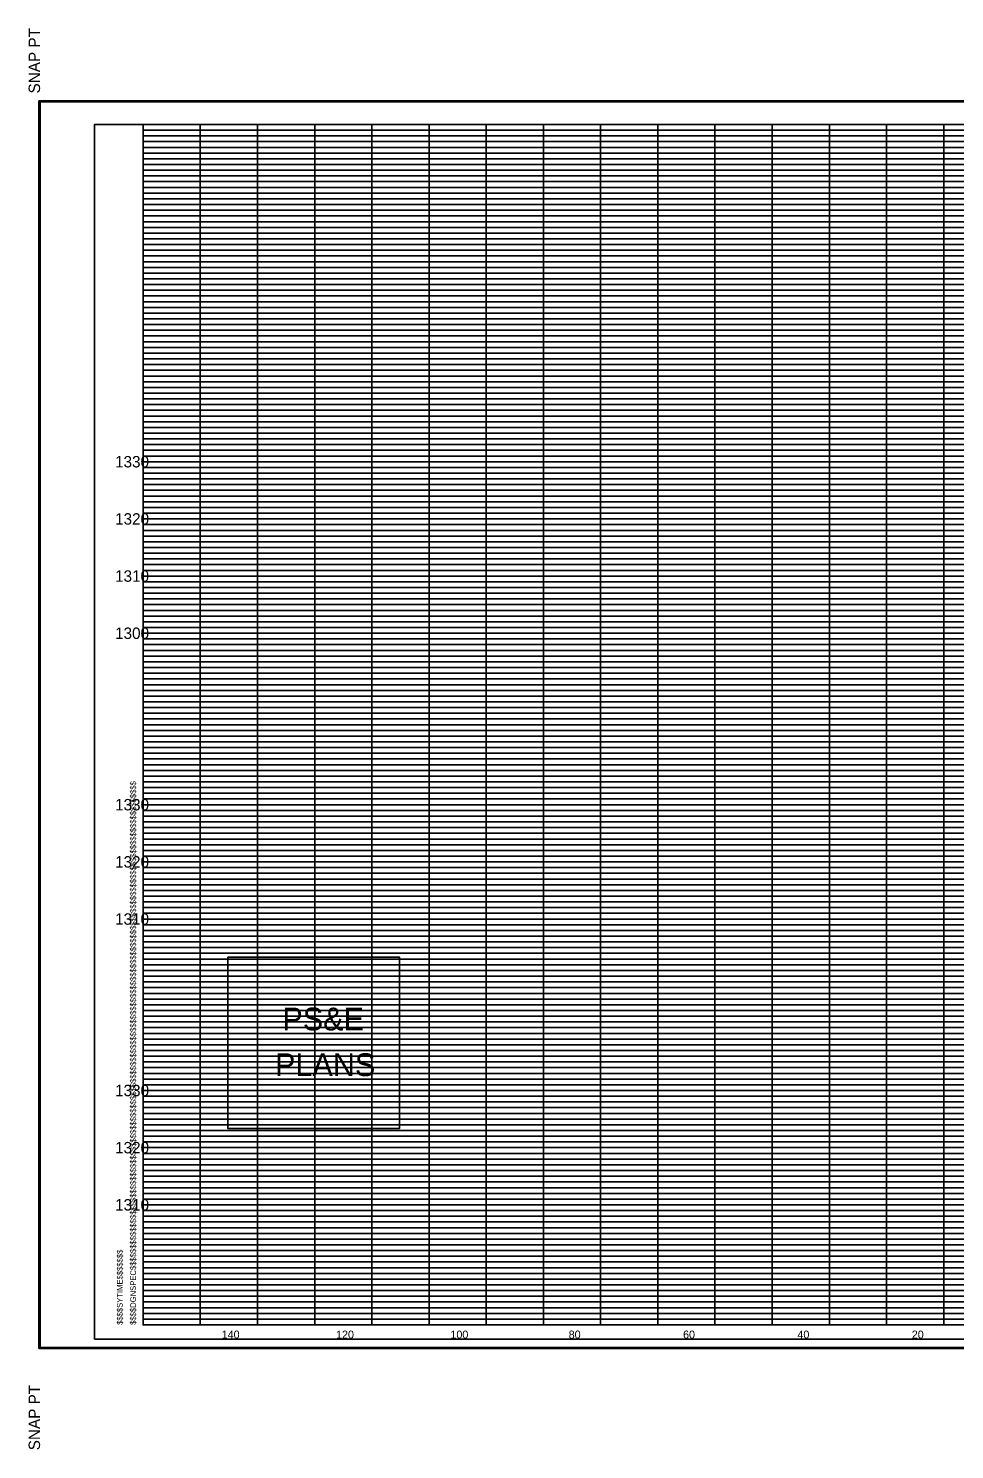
# Model space of a CAD drawing. Extents: x 980 to 1324, y 978 to 1227.
# Drawn here: x 979.7 to 1141.7, y 978 to 1226.6 of the extents above; entities that cross this region are included whole.
import ezdxf

# ---------------------------------------------------------------- set-up
doc = ezdxf.new("R2010")
doc.units = 0
for name, color, linetype in [('Default', 7, 'Continuous'), ('DESIGN - SHEET - Corner Text', 7, 'Continuous'), ('DESIGN - SHEET - Light Grid', 7, 'Continuous'), ('DESIGN - SHEET - Linework', 7, 'Continuous'), ('DESIGN - SHEET - Plot Shape', 7, 'Continuous'), ('DESIGN - TYPICAL - Text', 7, 'Continuous')]:
    doc.layers.add(name, color=color, linetype=linetype)

# ---------------------------------------------------------------- blocks, each defined once
blk = doc.blocks.new('XSTSHT')
at = {"layer": 'DESIGN - SHEET - Light Grid'}
for p, q in [((0, 20.9), (8, 20.9)), ((8, 20.9), (16, 20.9)), ((0, 20.8), (8, 20.8)), ((0, 20.7), (8, 20.7)), ((8, 20.8), (16, 20.8)), ((8, 20.7), (16, 20.7)), ((0, 20.6), (8, 20.6)), ((0, 20.5), (8, 20.5)), ((0, 20.4), (8, 20.4)), ((8, 20.6), (16, 20.6)), ((8, 20.5), (16, 20.5)), ((8, 20.4), (16, 20.4)), ((0, 20.3), (8, 20.3)), ((0, 20.2), (8, 20.2)), ((8, 20.3), (16, 20.3)), ((8, 20.2), (16, 20.2)), ((0, 20.1), (8, 20.1)), ((0, 19.9), (8, 19.9)), ((8, 20.1), (16, 20.1)), ((8, 19.9), (16, 19.9)), ((0, 19.8), (8, 19.8)), ((0, 19.7), (8, 19.7)), ((8, 19.8), (16, 19.8)), ((8, 19.7), (16, 19.7)), ((0, 19.6), (8, 19.6)), ((0, 19.5), (8, 19.5)), ((0, 19.4), (8, 19.4)), ((8, 19.6), (16, 19.6)), ((8, 19.5), (16, 19.5)), ((8, 19.4), (16, 19.4)), ((0, 19.3), (8, 19.3)), ((0, 19.2), (8, 19.2)), ((8, 19.3), (16, 19.3)), ((8, 19.2), (16, 19.2)), ((0, 19.1), (8, 19.1)), ((0, 18.9), (8, 18.9)), ((8, 19.1), (16, 19.1)), ((8, 18.9), (16, 18.9)), ((0, 18.8), (8, 18.8)), ((0, 18.7), (8, 18.7)), ((8, 18.8), (16, 18.8)), ((8, 18.7), (16, 18.7)), ((0, 18.6), (8, 18.6)), ((0, 18.5), (8, 18.5)), ((0, 18.4), (8, 18.4)), ((8, 18.6), (16, 18.6)), ((8, 18.5), (16, 18.5)), ((8, 18.4), (16, 18.4)), ((0, 18.3), (8, 18.3)), ((0, 18.2), (8, 18.2)), ((8, 18.3), (16, 18.3)), ((8, 18.2), (16, 18.2)), ((0, 18.1), (8, 18.1)), ((8, 18.1), (16, 18.1)), ((0, 17.9), (8, 17.9)), ((0, 17.8), (8, 17.8)), ((0, 17.7), (8, 17.7)), ((8, 17.9), (16, 17.9)), ((8, 17.8), (16, 17.8)), ((8, 17.7), (16, 17.7)), ((0, 17.6), (8, 17.6)), ((0, 17.5), (8, 17.5)), ((8, 17.6), (16, 17.6)), ((8, 17.5), (16, 17.5)), ((0, 17.4), (8, 17.4)), ((0, 17.3), (8, 17.3)), ((0, 17.2), (8, 17.2)), ((8, 17.4), (16, 17.4)), ((8, 17.3), (16, 17.3)), ((8, 17.2), (16, 17.2)), ((0, 17.1), (8, 17.1)), ((8, 17.1), (16, 17.1)), ((0, 16.9), (8, 16.9)), ((0, 16.8), (8, 16.8)), ((0, 16.7), (8, 16.7)), ((8, 16.9), (16, 16.9)), ((8, 16.8), (16, 16.8)), ((8, 16.7), (16, 16.7)), ((0, 16.6), (8, 16.6)), ((0, 16.5), (8, 16.5)), ((8, 16.6), (16, 16.6)), ((8, 16.5), (16, 16.5)), ((0, 16.4), (8, 16.4)), ((0, 16.3), (8, 16.3)), ((0, 16.2), (8, 16.2)), ((8, 16.4), (16, 16.4)), ((8, 16.3), (16, 16.3)), ((8, 16.2), (16, 16.2)), ((0, 16.1), (8, 16.1)), ((8, 16.1), (16, 16.1)), ((0, 15.9), (8, 15.9)), ((0, 15.8), (8, 15.8)), ((0, 15.7), (8, 15.7)), ((8, 15.9), (16, 15.9)), ((8, 15.8), (16, 15.8)), ((8, 15.7), (16, 15.7)), ((0, 15.6), (8, 15.6)), ((0, 15.5), (8, 15.5)), ((8, 15.6), (16, 15.6)), ((8, 15.5), (16, 15.5)), ((0, 15.4), (8, 15.4)), ((0, 15.3), (8, 15.3)), ((0, 15.2), (8, 15.2)), ((8, 15.4), (16, 15.4)), ((8, 15.3), (16, 15.3)), ((8, 15.2), (16, 15.2)), ((0, 15.1), (8, 15.1)), ((8, 15.1), (16, 15.1)), ((0, 14.9), (8, 14.9)), ((0, 14.8), (8, 14.8)), ((0, 14.7), (8, 14.7)), ((8, 14.9), (16, 14.9)), ((8, 14.8), (16, 14.8)), ((8, 14.7), (16, 14.7)), ((0, 14.6), (8, 14.6)), ((0, 14.5), (8, 14.5)), ((8, 14.6), (16, 14.6)), ((8, 14.5), (16, 14.5)), ((0, 14.4), (8, 14.4)), ((0, 14.3), (8, 14.3)), ((0, 14.2), (8, 14.2)), ((8, 14.4), (16, 14.4)), ((8, 14.3), (16, 14.3)), ((8, 14.2), (16, 14.2)), ((0, 14.1), (8, 14.1)), ((8, 14.1), (16, 14.1)), ((0, 13.9), (8, 13.9)), ((0, 13.8), (8, 13.8)), ((0, 13.7), (8, 13.7)), ((8, 13.9), (16, 13.9)), ((8, 13.8), (16, 13.8)), ((8, 13.7), (16, 13.7)), ((0, 13.6), (8, 13.6)), ((0, 13.5), (8, 13.5)), ((8, 13.6), (16, 13.6)), ((8, 13.5), (16, 13.5)), ((0, 13.4), (8, 13.4)), ((0, 13.3), (8, 13.3)), ((0, 13.2), (8, 13.2)), ((8, 13.4), (16, 13.4)), ((8, 13.3), (16, 13.3)), ((8, 13.2), (16, 13.2)), ((0, 13.1), (8, 13.1)), ((8, 13.1), (16, 13.1)), ((0, 12.9), (8, 12.9)), ((0, 12.8), (8, 12.8)), ((0, 12.7), (8, 12.7)), ((8, 12.9), (16, 12.9)), ((8, 12.8), (16, 12.8)), ((8, 12.7), (16, 12.7)), ((0, 12.6), (8, 12.6)), ((0, 12.5), (8, 12.5)), ((8, 12.6), (16, 12.6)), ((8, 12.5), (16, 12.5)), ((0, 12.4), (8, 12.4)), ((0, 12.3), (8, 12.3)), ((0, 12.2), (8, 12.2)), ((8, 12.4), (16, 12.4)), ((8, 12.3), (16, 12.3)), ((8, 12.2), (16, 12.2)), ((0, 12.1), (8, 12.1)), ((8, 12.1), (16, 12.1)), ((0, 11.9), (8, 11.9)), ((0, 11.8), (8, 11.8)), ((0, 11.7), (8, 11.7)), ((8, 11.9), (16, 11.9)), ((8, 11.8), (16, 11.8)), ((8, 11.7), (16, 11.7)), ((0, 11.6), (8, 11.6)), ((0, 11.5), (8, 11.5)), ((8, 11.6), (16, 11.6)), ((8, 11.5), (16, 11.5)), ((0, 11.4), (8, 11.4)), ((0, 11.3), (8, 11.3)), ((0, 11.2), (8, 11.2)), ((8, 11.4), (16, 11.4)), ((8, 11.3), (16, 11.3)), ((8, 11.2), (16, 11.2)), ((0, 11.1), (8, 11.1)), ((8, 11.1), (16, 11.1)), ((0, 10.9), (8, 10.9)), ((0, 10.8), (8, 10.8)), ((0, 10.7), (8, 10.7)), ((8, 10.9), (16, 10.9)), ((8, 10.8), (16, 10.8)), ((8, 10.7), (16, 10.7)), ((0, 10.6), (8, 10.6)), ((0, 10.5), (8, 10.5)), ((8, 10.6), (16, 10.6)), ((8, 10.5), (16, 10.5)), ((0, 10.4), (8, 10.4)), ((0, 10.3), (8, 10.3)), ((0, 10.2), (8, 10.2)), ((8, 10.4), (16, 10.4)), ((8, 10.3), (16, 10.3)), ((8, 10.2), (16, 10.2)), ((0, 10.1), (8, 10.1)), ((8, 10.1), (16, 10.1)), ((0, 9.9), (8, 9.9)), ((0, 9.8), (8, 9.8)), ((0, 9.7), (8, 9.7)), ((8, 9.9), (16, 9.9)), ((8, 9.8), (16, 9.8)), ((8, 9.7), (16, 9.7)), ((0, 9.6), (8, 9.6)), ((0, 9.5), (8, 9.5)), ((8, 9.6), (16, 9.6)), ((8, 9.5), (16, 9.5)), ((0, 9.4), (8, 9.4)), ((0, 9.3), (8, 9.3)), ((0, 9.2), (8, 9.2)), ((8, 9.4), (16, 9.4)), ((8, 9.3), (16, 9.3)), ((8, 9.2), (16, 9.2)), ((0, 9.1), (8, 9.1)), ((8, 9.1), (16, 9.1)), ((0, 8.9), (8, 8.9)), ((0, 8.8), (8, 8.8)), ((8, 8.9), (16, 8.9)), ((8, 8.8), (16, 8.8)), ((0, 8.7), (8, 8.7)), ((0, 8.6), (8, 8.6)), ((0, 8.5), (8, 8.5)), ((8, 8.7), (16, 8.7)), ((8, 8.6), (16, 8.6)), ((8, 8.5), (16, 8.5)), ((0, 8.4), (8, 8.4)), ((0, 8.3), (8, 8.3)), ((8, 8.4), (16, 8.4)), ((8, 8.3), (16, 8.3)), ((0, 8.2), (8, 8.2)), ((0, 8.1), (8, 8.1)), ((8, 8.2), (16, 8.2)), ((8, 8.1), (16, 8.1)), ((0, 7.9), (8, 7.9)), ((0, 7.8), (8, 7.8)), ((8, 7.9), (16, 7.9)), ((8, 7.8), (16, 7.8)), ((0, 7.7), (8, 7.7)), ((0, 7.6), (8, 7.6)), ((0, 7.5), (8, 7.5)), ((8, 7.7), (16, 7.7)), ((8, 7.6), (16, 7.6)), ((8, 7.5), (16, 7.5)), ((0, 7.4), (8, 7.4)), ((0, 7.3), (8, 7.3)), ((8, 7.4), (16, 7.4)), ((8, 7.3), (16, 7.3)), ((0, 7.2), (8, 7.2)), ((0, 7.1), (8, 7.1)), ((8, 7.2), (16, 7.2)), ((8, 7.1), (16, 7.1)), ((0, 6.9), (8, 6.9)), ((0, 6.8), (8, 6.8)), ((8, 6.9), (16, 6.9)), ((8, 6.8), (16, 6.8)), ((0, 6.7), (8, 6.7)), ((0, 6.6), (8, 6.6)), ((0, 6.5), (8, 6.5)), ((8, 6.7), (16, 6.7)), ((8, 6.6), (16, 6.6)), ((8, 6.5), (16, 6.5)), ((0, 6.4), (8, 6.4)), ((0, 6.3), (8, 6.3)), ((8, 6.4), (16, 6.4)), ((8, 6.3), (16, 6.3)), ((0, 6.2), (8, 6.2)), ((0, 6.1), (8, 6.1)), ((8, 6.2), (16, 6.2)), ((8, 6.1), (16, 6.1)), ((0, 5.9), (8, 5.9)), ((0, 5.8), (8, 5.8)), ((8, 5.9), (16, 5.9)), ((8, 5.8), (16, 5.8)), ((0, 5.7), (8, 5.7)), ((0, 5.6), (8, 5.6)), ((0, 5.5), (8, 5.5)), ((8, 5.7), (16, 5.7)), ((8, 5.6), (16, 5.6)), ((8, 5.5), (16, 5.5)), ((0, 5.4), (8, 5.4)), ((0, 5.3), (8, 5.3)), ((8, 5.4), (16, 5.4)), ((8, 5.3), (16, 5.3)), ((0, 5.2), (8, 5.2)), ((0, 5.1), (8, 5.1)), ((8, 5.2), (16, 5.2)), ((8, 5.1), (16, 5.1)), ((0, 4.9), (8, 4.9)), ((0, 4.8), (8, 4.8)), ((8, 4.9), (16, 4.9)), ((8, 4.8), (16, 4.8)), ((0, 4.7), (8, 4.7)), ((0, 4.6), (8, 4.6)), ((0, 4.5), (8, 4.5)), ((8, 4.7), (16, 4.7)), ((8, 4.6), (16, 4.6)), ((8, 4.5), (16, 4.5)), ((0, 4.4), (8, 4.4)), ((0, 4.3), (8, 4.3)), ((8, 4.4), (16, 4.4)), ((8, 4.3), (16, 4.3)), ((0, 4.2), (8, 4.2)), ((0, 4.1), (8, 4.1)), ((8, 4.2), (16, 4.2)), ((8, 4.1), (16, 4.1)), ((0, 3.9), (8, 3.9)), ((0, 3.8), (8, 3.8)), ((8, 3.9), (16, 3.9)), ((8, 3.8), (16, 3.8)), ((0, 3.7), (8, 3.7)), ((0, 3.6), (8, 3.6)), ((0, 3.5), (8, 3.5)), ((8, 3.7), (16, 3.7)), ((8, 3.6), (16, 3.6)), ((8, 3.5), (16, 3.5)), ((0, 3.4), (8, 3.4)), ((0, 3.3), (8, 3.3)), ((8, 3.4), (16, 3.4)), ((8, 3.3), (16, 3.3)), ((0, 3.2), (8, 3.2)), ((0, 3.1), (8, 3.1)), ((8, 3.2), (16, 3.2)), ((8, 3.1), (16, 3.1)), ((0, 2.9), (8, 2.9)), ((0, 2.8), (8, 2.8)), ((8, 2.9), (16, 2.9)), ((8, 2.8), (16, 2.8)), ((0, 2.7), (8, 2.7)), ((0, 2.6), (8, 2.6)), ((0, 2.5), (8, 2.5)), ((8, 2.7), (16, 2.7)), ((8, 2.6), (16, 2.6)), ((8, 2.5), (16, 2.5)), ((0, 2.4), (8, 2.4)), ((0, 2.3), (8, 2.3)), ((8, 2.4), (16, 2.4)), ((8, 2.3), (16, 2.3)), ((0, 2.2), (8, 2.2)), ((0, 2.1), (8, 2.1)), ((8, 2.2), (16, 2.2)), ((8, 2.1), (16, 2.1)), ((0, 1.9), (8, 1.9)), ((0, 1.8), (8, 1.8)), ((8, 1.9), (16, 1.9)), ((8, 1.8), (16, 1.8)), ((0, 1.7), (8, 1.7)), ((0, 1.6), (8, 1.6)), ((0, 1.5), (8, 1.5)), ((8, 1.7), (16, 1.7)), ((8, 1.6), (16, 1.6)), ((8, 1.5), (16, 1.5)), ((0, 1.4), (8, 1.4)), ((0, 1.3), (8, 1.3)), ((8, 1.4), (16, 1.4)), ((8, 1.3), (16, 1.3)), ((0, 1.2), (8, 1.2)), ((0, 1.1), (8, 1.1)), ((8, 1.2), (16, 1.2)), ((8, 1.1), (16, 1.1)), ((0, 0.9), (8, 0.9)), ((0, 0.8), (8, 0.8)), ((8, 0.9), (16, 0.9)), ((8, 0.8), (16, 0.8)), ((0, 0.7), (8, 0.7)), ((0, 0.6), (8, 0.6)), ((0, 0.5), (8, 0.5)), ((8, 0.7), (16, 0.7)), ((8, 0.6), (16, 0.6)), ((8, 0.5), (16, 0.5)), ((0, 0.4), (8, 0.4)), ((0, 0.3), (8, 0.3)), ((8, 0.4), (16, 0.4)), ((8, 0.3), (16, 0.3)), ((0, 0.2), (8, 0.2)), ((0, 0.1), (8, 0.1)), ((8, 0.2), (16, 0.2)), ((8, 0.1), (16, 0.1))]:
    blk.add_line(p, q, dxfattribs=at)
at = {"layer": 'DESIGN - SHEET - Linework'}
for p, q in [((-1.823, -0.414), (-1.823, 21.414)), ((-1.823, 21.414), (32.217, 21.414)), ((1, 0), (1, 21)), ((2, 0), (2, 21)), ((3, 0), (3, 21)), ((4, 0), (4, 21)), ((5, 0), (5, 21)), ((6, 0), (6, 21)), ((7, 0), (7, 21)), ((8, 0), (8, 21)), ((9, 0), (9, 21)), ((10, 0), (10, 21)), ((11, 0), (11, 21)), ((12, 0), (12, 21)), ((13, 0), (13, 21)), ((14, 0), (14, 21)), ((0, 20), (28, 20)), ((0, 19), (32, 19)), ((0, 18), (32, 18)), ((0, 17), (32, 17)), ((0, 16), (32, 16)), ((0, 15), (32, 15)), ((0, 14), (32, 14)), ((0, 13), (32, 13)), ((0, 12), (32, 12)), ((0, 11), (32, 11)), ((0, 10), (32, 10)), ((0, 9), (32, 9)), ((0, 8), (32, 8)), ((0, 7), (32, 7)), ((0, 6), (32, 6)), ((0, 5), (32, 5)), ((0, 4), (32, 4)), ((0, 3), (32, 3)), ((0, 2), (32, 2)), ((0, 1), (32, 1)), ((-1.823, -0.414), (32.217, -0.414))]:
    blk.add_line(p, q, dxfattribs=at)
blk.add_lwpolyline([(0, 21), (0, 0), (32, 0), (32, 21), (0, 21)], dxfattribs=at)
at = {"layer": 'DESIGN - SHEET - Plot Shape'}
for points in [[(-1.803, 21.394), (32.197, 21.394), (32.197, -0.394), (-1.803, -0.394)], [(-0.85, 21), (32, 21), (32, -0.25), (-0.85, -0.25)]]:
    blk.add_lwpolyline(points, close=True, dxfattribs=at)
at = {"layer": 'DESIGN - SHEET - Corner Text'}
for s, height, p in [('  SNAP PT', 0.2, (-1.803, 21.394)), ('$$$$DGNSPEC$$$$$$$$$$$$$$$$$$$$$$$$$$$$$$$$$$$$$$$$$$$$$$$$$$$$$$$$$$$$$$$$$$$$$$$$$$$$$$$$$$$$$$$$$$$$$$$$$$$$$$$$$$$$$$$$$$$', 0.100002, (-0.126, 0)), ('$$$$SYTIME$$$$$$$', 0.1, (-0.358, 0)), ('SNAP PT  ', 0.2, (-1.803, -2.194))]:
    blk.add_text(s, height=height, rotation=90, dxfattribs=at).set_placement(p)

msp = doc.modelspace()

# ---------------------------------------------------------------- linework, layer by layer
at = {"layer": 'DESIGN - SHEET - Corner Text'}
msp.add_lwpolyline([(1014.63, 1064.14), (1014.63, 1034.14), (1044.63, 1034.14), (1044.63, 1064.14)], close=True, dxfattribs=at)
at = {"layer": 'DESIGN - SHEET - Plot Shape'}
msp.add_lwpolyline([(991.3, 997.3), (1319.8, 997.3), (1319.8, 1209.8), (991.3, 1209.8)], close=True, dxfattribs=at)

# ---------------------------------------------------------------- block references
at = {"layer": 'Default', "xscale": 10, "yscale": 10}
msp.add_blockref('XSTSHT', (999.8, 999.8), dxfattribs=at)

# ---------------------------------------------------------------- texts
at = {"layer": 'DESIGN - SHEET - Corner Text'}
for s, p in [('PS&E', (1024.15, 1051.31)), ('PLANS', (1022.86, 1043.31))]:
    msp.add_text(s, height=4, dxfattribs=at).set_placement(p)
at = {"layer": 'DESIGN - TYPICAL - Text'}
for s, height, p in [('     1330     ', 2, (991.17, 1149.8)), ('     1320     ', 2, (991.17, 1139.8)), ('     1310     ', 2, (991.17, 1129.8)), ('     1300     ', 2, (991.17, 1119.8)), ('     1330     ', 2, (991.17, 1089.8)), ('     1320     ', 2, (991.17, 1079.8)), ('     1310     ', 2, (991.17, 1069.8)), ('     1330     ', 2, (991.17, 1039.8)), ('     1320     ', 2, (991.17, 1029.8)), ('     1310     ', 2, (991.17, 1019.8)), ('     140     ', 1.4, (1010.94, 997.4)), ('     140     ', 1.4, (1010.94, 997.4)), ('     120     ', 1.4, (1030.94, 997.4)), ('     120     ', 1.4, (1030.94, 997.4)), ('     100     ', 1.4, (1050.94, 997.4)), ('     100     ', 1.4, (1050.94, 997.4)), ('     80     ', 1.4, (1071.62, 997.4)), ('     80     ', 1.4, (1071.62, 997.4)), ('     60     ', 1.4, (1091.62, 997.4)), ('     60     ', 1.4, (1091.62, 997.4)), ('     40     ', 1.4, (1111.62, 997.4)), ('     40     ', 1.4, (1111.62, 997.4)), ('     20     ', 1.4, (1131.62, 997.4)), ('     20     ', 1.4, (1131.62, 997.4))]:
    msp.add_text(s, height=height, dxfattribs=at).set_placement(p)

doc.saveas('drawing.dxf')
